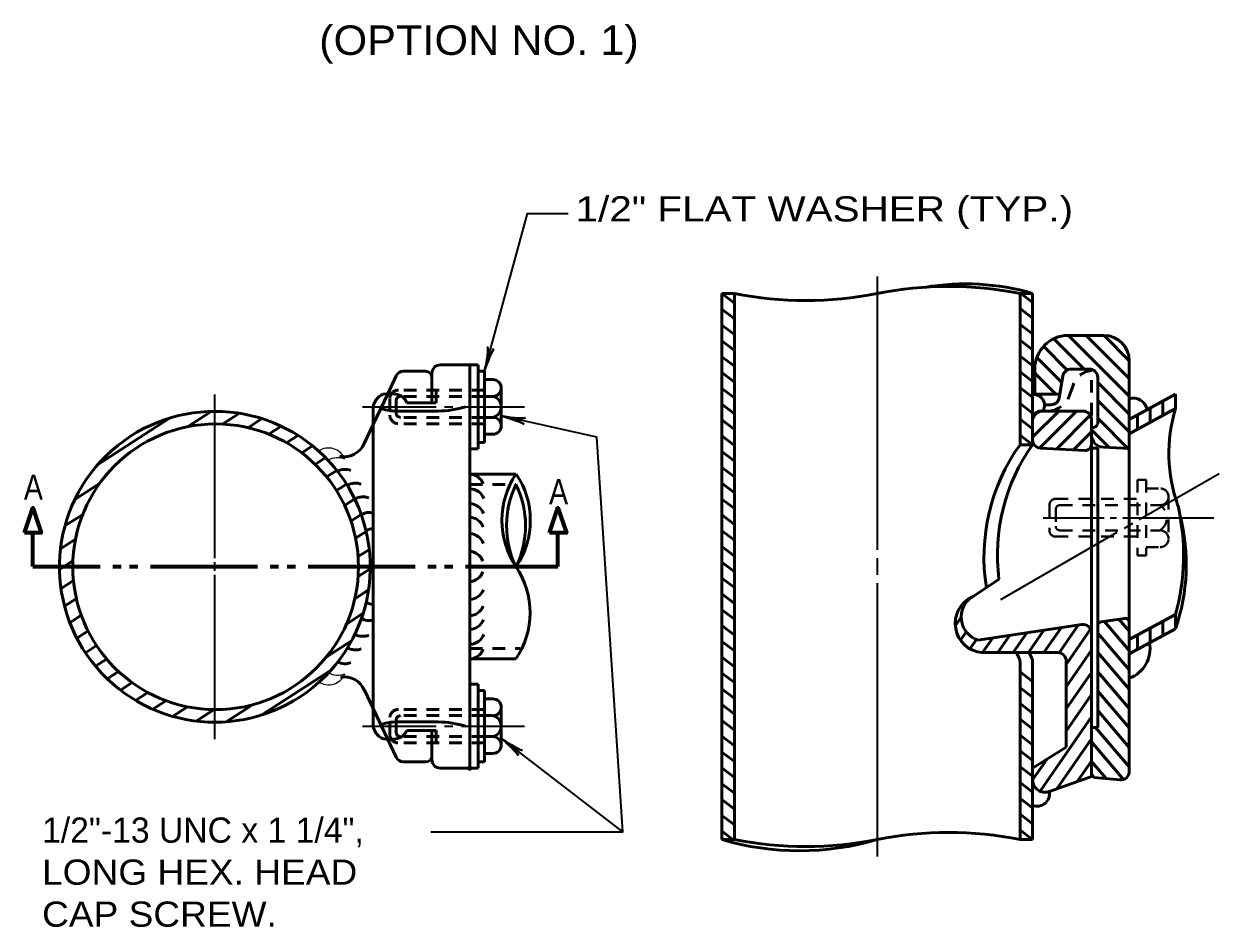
# Model space of a CAD drawing. Extents: x -1 to 679, y 1 to 441.
# Drawn here: x 364.9 to 507.1, y 223.3 to 330.8 of the extents above; entities that cross this region are included whole.
import ezdxf
from ezdxf.enums import TextEntityAlignment as Align

# ---------------------------------------------------------------- set-up
doc = ezdxf.new("R2010")
doc.units = 0
doc.header["$PDMODE"] = 32
doc.header["$PDSIZE"] = 0.5
doc.linetypes.add('LONG_DASHED', pattern=[7.5, 6, -1.5])
doc.linetypes.add('SHORT_DASHED', pattern=[2.7, 1.5, -1.2])
doc.layers.add('1', color=7, linetype='Continuous', lineweight=13)

msp = doc.modelspace()

# ---------------------------------------------------------------- linework, layer by layer
at = {"layer": '1', "lineweight": 35}
for p, q in [((466.424, 300.739), (466.424, 268.239)), ((387.59, 267.239), (387.59, 286.708)), ((405.174, 285.239), (413.924, 285.239)), ((414.924, 285.239), (415.924, 285.239)), ((416.924, 285.239), (424.424, 285.239)), ((497.597, 271.818), (507.123, 277.318)), ((486.174, 272.043), (493.424, 272.043)), ((494.174, 272.043), (494.924, 272.043)), ((495.674, 272.043), (506.516, 272.043)), ((481.142, 262.318), (494.999, 270.318)), ((495.865, 270.818), (496.848, 271.385)), ((387.59, 265.739), (387.59, 266.739)), ((466.424, 267.239), (466.424, 265.239)), ((387.59, 245.708), (387.59, 265.239)), ((466.424, 264.239), (466.424, 231.739)), ((405.174, 247.239), (413.924, 247.239)), ((414.924, 247.239), (415.924, 247.239)), ((416.924, 247.239), (424.424, 247.239))]:
    msp.add_line(p, q, dxfattribs=at)
at = {"layer": '1', "lineweight": 53}
for p, q in [((484.924, 297.679), (483.424, 298.816)), ((447.924, 298.739), (447.924, 233.739)), ((447.924, 298.739), (449.424, 298.739)), ((449.424, 297.602), (447.924, 298.739)), ((449.424, 298.739), (449.424, 233.739)), ((483.424, 298.739), (484.924, 298.739)), ((483.424, 298.739), (483.424, 280.739)), ((449.424, 295.72), (447.924, 296.857)), ((484.924, 295.796), (483.424, 296.933)), ((449.424, 293.837), (447.924, 294.974)), ((484.924, 293.914), (483.424, 295.051)), ((449.424, 291.955), (447.924, 293.092)), ((484.924, 292.032), (483.424, 293.169)), ((487.451, 293.348), (491.06, 289.739)), ((489.174, 293.739), (493.424, 293.739)), ((489.182, 293.739), (496.424, 286.496)), ((491.303, 293.739), (496.424, 288.618)), ((493.424, 293.739), (496.424, 290.739)), ((486.231, 292.447), (489.055, 289.623)), ((414.424, 290.239), (418.924, 290.239)), ((417.924, 290.239), (417.924, 242.239)), ((418.924, 280.239), (418.924, 290.239)), ((449.424, 290.073), (447.924, 291.21)), ((484.924, 290.15), (483.424, 291.287)), ((485.425, 291.132), (488.409, 288.147)), ((496.424, 290.739), (496.424, 283.739)), ((408.155, 286.81), (409.153, 288.917)), ((410.057, 289.489), (412.674, 289.489)), ((413.424, 289.239), (413.424, 285.739)), ((419.674, 289.489), (418.924, 289.489)), ((419.674, 280.989), (419.674, 289.489)), ((449.424, 288.191), (447.924, 289.328)), ((484.924, 288.268), (483.424, 289.405)), ((485.174, 289.739), (485.174, 286.739)), ((485.174, 289.261), (487.696, 286.739)), ((488.535, 288.903), (488.105, 286.324)), ((489.521, 289.739), (491.674, 289.739)), ((420.674, 288.489), (419.674, 288.489)), ((421.674, 287.489), (421.674, 282.989)), ((449.424, 286.308), (447.924, 287.445)), ((484.924, 286.385), (483.424, 287.522)), ((492.674, 288.739), (492.674, 283.239)), ((492.674, 288.125), (496.424, 284.375)), ((413.924, 285.739), (413.924, 287.239)), ((420.674, 286.489), (419.674, 286.489)), ((485.174, 286.739), (488.174, 286.739)), ((492.674, 286.003), (496.424, 282.253)), ((496.424, 283.739), (501.924, 286.739)), ((501.924, 286.739), (501.924, 285.03)), ((384.33, 282.876), (387.16, 284.703)), ((406.424, 284.989), (406.424, 247.489)), ((414.174, 284.739), (409.674, 284.739)), ((413.924, 285.739), (410.424, 285.739)), ((449.424, 284.426), (447.924, 285.563)), ((484.924, 284.503), (483.424, 285.64)), ((488.046, 284.739), (484.924, 281.618)), ((485.065, 284.376), (485.46, 284.639)), ((490.167, 284.739), (485.763, 280.335)), ((485.924, 284.739), (490.924, 284.739)), ((487.119, 285.489), (486.348, 285.481)), ((496.424, 282.03), (501.924, 285.03)), ((498.924, 285.102), (498.924, 283.394)), ((500.424, 285.921), (500.424, 284.212)), ((373.621, 278.343), (382.08, 283.804)), ((388.501, 283.188), (390.499, 284.478)), ((391.532, 282.764), (393.195, 283.838)), ((405.352, 280.892), (406.424, 283.156)), ((420.674, 283.989), (419.674, 283.989)), ((449.424, 282.544), (447.924, 283.681)), ((484.924, 282.621), (483.424, 283.758)), ((485.355, 284.534), (485.223, 284.402)), ((491.789, 284.24), (487.772, 280.223)), ((491.924, 283.739), (491.924, 280.077)), ((492.674, 283.882), (496.424, 280.132)), ((497.424, 284.284), (497.424, 282.576)), ((394.01, 281.983), (395.488, 282.937)), ((396.117, 280.963), (397.479, 281.843)), ((420.674, 281.989), (419.674, 281.989)), ((449.424, 280.662), (447.924, 281.799)), ((484.924, 280.739), (483.424, 281.876)), ((491.924, 282.254), (489.787, 280.117)), ((491.924, 282.511), (494.042, 280.393)), ((397.939, 279.759), (399.226, 280.59)), ((419.674, 280.989), (418.924, 280.989)), ((483.424, 280.739), (484.924, 280.739)), ((485.872, 280.323), (491.135, 280.046)), ((492.674, 280.315), (491.924, 280.315)), ((493.345, 280.43), (496.424, 280.268)), ((399.522, 278.4), (400.76, 279.2)), ((417.924, 280.239), (418.924, 280.239)), ((449.424, 278.779), (447.924, 279.916)), ((491.924, 280.077), (491.924, 241.591)), ((400.889, 276.902), (402.1, 277.684)), ((449.424, 276.897), (447.924, 278.034)), ((370.911, 274.213), (373.861, 276.117)), ((402.055, 275.274), (403.255, 276.049)), ((417.924, 277.239), (423.424, 277.239)), ((449.424, 275.015), (447.924, 276.152)), ((403.022, 273.518), (404.228, 274.296)), ((449.424, 273.133), (447.924, 274.27)), ((369.742, 271.077), (371.859, 272.444)), ((403.786, 271.631), (405.014, 272.424)), ((449.424, 271.251), (447.924, 272.388)), ((404.332, 269.602), (405.603, 270.423)), ((449.424, 269.368), (447.924, 270.505)), ((369.215, 268.356), (370.998, 269.507)), ((404.631, 267.415), (405.973, 268.282)), ((449.424, 267.486), (447.924, 268.623)), ((369.092, 265.897), (370.69, 266.928)), ((449.424, 265.604), (447.924, 266.741)), ((404.634, 265.036), (406.088, 265.975)), ((449.424, 263.722), (447.924, 264.859)), ((480.924, 264.739), (477.76, 262.63)), ((369.27, 263.631), (370.752, 264.587)), ((404.243, 262.403), (405.885, 263.464)), ((369.693, 261.523), (371.099, 262.431)), ((449.424, 261.839), (447.924, 262.976)), ((370.328, 259.553), (371.686, 260.43)), ((403.241, 259.376), (405.241, 260.667)), ((449.424, 259.957), (447.924, 261.094)), ((496.424, 257.54), (501.924, 260.54)), ((501.924, 260.54), (501.924, 258.831)), ((449.424, 258.075), (447.924, 259.212)), ((475.728, 259.214), (476.425, 260.223)), ((478.424, 257.489), (490.778, 259.319)), ((486.262, 255.989), (488.311, 258.954)), ((488.077, 255.977), (490.342, 259.254)), ((493.101, 259.663), (495.851, 260.071)), ((493.448, 259.715), (496.424, 256.241)), ((495.195, 259.981), (496.457, 258.509)), ((500.424, 259.722), (500.424, 258.013)), ((371.158, 257.708), (372.488, 258.567)), ((476.345, 257.468), (477.029, 258.457)), ((477.461, 256.444), (478.23, 257.558)), ((478.969, 255.989), (480.186, 257.75)), ((480.793, 255.989), (482.217, 258.051)), ((482.616, 255.989), (484.248, 258.352)), ((484.439, 255.989), (486.28, 258.653)), ((488.924, 254.564), (491.825, 258.763)), ((492.674, 258.312), (496.424, 253.936)), ((496.424, 255.831), (501.924, 258.831)), ((497.424, 258.085), (497.424, 256.377)), ((498.924, 258.903), (498.924, 257.195)), ((372.173, 255.982), (373.492, 256.834)), ((400.826, 255.436), (403.854, 257.391)), ((449.424, 256.193), (447.924, 257.33)), ((488.924, 251.925), (491.924, 256.267)), ((496.424, 255.831), (498.841, 257.149)), ((373.369, 254.374), (374.694, 255.23)), ((417.924, 255.239), (423.424, 255.239)), ((449.424, 254.31), (447.924, 255.447)), ((478.924, 255.989), (487.924, 255.989)), ((483.424, 233.739), (483.424, 254.739)), ((484.924, 254.739), (484.924, 237.449)), ((488.924, 254.989), (488.924, 244.739)), ((492.674, 256.007), (496.424, 251.631)), ((496.424, 255.831), (496.424, 241.836)), ((496.424, 252.937), (496.424, 255.831)), ((374.753, 252.887), (376.1, 253.757)), ((393.17, 248.569), (401.368, 253.862)), ((449.424, 252.428), (447.924, 253.565)), ((484.924, 252.561), (483.424, 253.698)), ((488.924, 249.286), (491.924, 253.628)), ((492.674, 253.702), (496.424, 249.325)), ((376.333, 251.527), (377.724, 252.424)), ((417.924, 252.239), (418.924, 252.239)), ((418.924, 252.239), (418.924, 242.239)), ((378.133, 250.308), (379.594, 251.251)), ((405.388, 251.51), (406.424, 249.322)), ((419.674, 251.489), (418.924, 251.489)), ((419.674, 251.489), (419.674, 242.989)), ((420.674, 250.489), (419.674, 250.489)), ((449.424, 250.546), (447.924, 251.683)), ((484.924, 250.679), (483.424, 251.816)), ((488.924, 246.647), (491.924, 250.99)), ((492.674, 251.396), (496.424, 247.02)), ((380.187, 249.254), (381.761, 250.27)), ((382.56, 248.405), (384.321, 249.542)), ((385.374, 247.841), (387.493, 249.209)), ((388.93, 247.756), (392.077, 249.788)), ((421.674, 244.989), (421.674, 249.489)), ((449.424, 248.664), (447.924, 249.801)), ((484.924, 248.796), (483.424, 249.933)), ((492.674, 249.091), (496.424, 244.715)), ((414.174, 247.739), (409.674, 247.739)), ((420.674, 248.489), (419.674, 248.489)), ((449.424, 246.781), (447.924, 247.918)), ((484.924, 246.914), (483.424, 248.051)), ((485.809, 239.499), (491.924, 248.351)), ((413.924, 246.739), (410.424, 246.739)), ((413.424, 243.239), (413.424, 246.739)), ((413.924, 246.739), (413.924, 245.239)), ((484.924, 245.032), (483.424, 246.169)), ((492.674, 247.091), (491.924, 247.091)), ((492.413, 247.091), (496.424, 242.409)), ((408.155, 245.668), (409.153, 243.561)), ((420.674, 245.989), (419.674, 245.989)), ((449.424, 244.899), (447.924, 246.036)), ((484.924, 242.239), (488.924, 244.739)), ((487.821, 239.773), (491.924, 245.712)), ((491.924, 245.356), (495.75, 240.89)), ((420.674, 243.989), (419.674, 243.989)), ((449.424, 243.017), (447.924, 244.154)), ((484.924, 243.15), (483.424, 244.287)), ((484.924, 240.858), (486.603, 243.288)), ((410.057, 242.989), (412.674, 242.989)), ((414.424, 242.239), (418.924, 242.239)), ((419.674, 242.989), (418.924, 242.989)), ((449.424, 241.135), (447.924, 242.272)), ((484.924, 241.268), (483.424, 242.405)), ((490.242, 240.638), (491.924, 243.073)), ((491.924, 243.05), (493.69, 240.99)), ((484.924, 239.385), (483.424, 240.522)), ((484.924, 240.867), (484.924, 233.739)), ((484.925, 237.816), (484.924, 240.867)), ((484.925, 237.816), (484.924, 240.867)), ((486.929, 239.455), (492.034, 241.278)), ((491.924, 241.591), (492.256, 241.12)), ((492.256, 241.12), (495.333, 240.84)), ((449.424, 239.253), (447.924, 240.39)), ((486.929, 239.455), (487.01, 239.484)), ((449.424, 237.37), (447.924, 238.507)), ((484.924, 237.503), (483.424, 238.64)), ((449.424, 235.488), (447.924, 236.625)), ((484.924, 235.621), (483.424, 236.758)), ((484.924, 233.739), (483.424, 234.876)), ((449.249, 233.739), (447.924, 234.743)), ((447.924, 233.739), (449.424, 233.739)), ((483.424, 233.739), (484.924, 233.739))]:
    msp.add_line(p, q, dxfattribs=at)
at = {"layer": '1', "linetype": 'SHORT_DASHED', "lineweight": 53}
for p, q in [((491.924, 284.231), (491.924, 289.565)), ((489.682, 287.586), (489.277, 286.502)), ((408.424, 286.239), (408.424, 284.239)), ((409.174, 284.489), (409.174, 285.989)), ((419.674, 287.239), (409.424, 287.239)), ((419.674, 286.489), (409.674, 286.489)), ((419.674, 283.239), (409.424, 283.239)), ((419.674, 283.989), (409.674, 283.989)), ((417.924, 275.989), (423.424, 275.989)), ((417.924, 256.489), (423.924, 256.489)), ((419.674, 249.239), (409.424, 249.239)), ((408.424, 246.239), (408.424, 248.239)), ((409.174, 247.989), (409.174, 246.489)), ((419.674, 248.489), (409.674, 248.489)), ((419.674, 245.239), (409.424, 245.239)), ((419.674, 245.989), (409.674, 245.989))]:
    msp.add_line(p, q, dxfattribs=at)
at = {"layer": '1', "linetype": 'LONG_DASHED', "lineweight": 53}
for p, q in [((406.424, 283.155), (408.155, 286.81)), ((406.424, 249.322), (408.155, 245.668))]:
    msp.add_line(p, q, dxfattribs=at)
at = {"layer": '1', "linetype": 'SHORT_DASHED', "lineweight": 40}
for p, q in [((497.424, 276.543), (498.424, 276.543)), ((497.424, 276.543), (497.424, 267.543)), ((498.424, 276.543), (498.424, 267.543)), ((498.424, 275.543), (500.108, 275.543)), ((486.924, 273.543), (486.924, 270.543)), ((487.674, 274.293), (497.424, 274.293)), ((488.174, 273.543), (500.108, 273.543)), ((501.108, 274.543), (501.108, 269.543)), ((487.674, 273.043), (487.674, 271.043)), ((488.174, 270.543), (500.108, 270.543)), ((487.674, 269.793), (497.424, 269.793)), ((497.424, 267.543), (498.424, 267.543)), ((498.424, 268.543), (500.108, 268.543))]:
    msp.add_line(p, q, dxfattribs=at)
at = {"layer": '1', "lineweight": 70}
for p, q in [((365.924, 266.239), (365.924, 270.239)), ((428.424, 266.239), (428.424, 270.239)), ((365.924, 266.239), (373.924, 266.239)), ((375.424, 266.239), (376.424, 266.239)), ((377.424, 266.239), (378.424, 266.239)), ((379.924, 266.239), (392.674, 266.239)), ((394.174, 266.239), (395.174, 266.239)), ((396.174, 266.239), (397.174, 266.239)), ((398.674, 266.239), (411.424, 266.239)), ((412.924, 266.239), (413.924, 266.239)), ((414.924, 266.239), (415.924, 266.239)), ((417.424, 266.239), (428.424, 266.239))]:
    msp.add_line(p, q, dxfattribs=at)
at = {"layer": '1'}
msp.add_line((379.924, 266.239), (392.674, 266.239), dxfattribs=at)
at = {"layer": '1', "lineweight": 35}
for points in [[(419.674, 289.489), (424.788, 308.252), (429.637, 308.252)], [(436.166, 234.649), (433.067, 281.622), (421.674, 284.168)], [(413.283, 234.649), (436.166, 234.649), (421.674, 245.791)]]:
    msp.add_lwpolyline(points, dxfattribs=at)
at = {"layer": '1', "lineweight": 53}
for points in [[(484.924, 298.739), (484.924, 283.739), (484.924, 280.739)], [(484.924, 283.739), (484.924, 287.045), (484.95, 286.705)], [(498.601, 284.926), (496.424, 283.739), (496.424, 286.212), (496.424, 286.212)], [(486.168, 284.778), (486.064, 284.787), (485.433, 284.608), (485.565, 284.618), (485.367, 284.533), (485.264, 284.429), (485.339, 284.401), (485.103, 284.307), (484.962, 283.911)], [(486.003, 284.739), (485.924, 284.739), (486.173, 284.802)], [(496.424, 283.739), (496.424, 282.03), (496.424, 257.54), (496.424, 255.831)], [(492.674, 280.315), (492.674, 259.168), (492.674, 247.091)]]:
    msp.add_lwpolyline(points, dxfattribs=at)
at = {"layer": '1', "lineweight": 70}
for points in [[(364.924, 270.239), (365.924, 273.239), (366.924, 270.239)], [(427.424, 270.239), (428.424, 273.239), (429.424, 270.239)]]:
    msp.add_lwpolyline(points, close=True, dxfattribs=at)
at = {"layer": '1', "lineweight": 53}
msp.add_circle((387.674, 266.208), 17, dxfattribs=at)
for centre, radius, start, end in [((474.924, 256.102), 43.476, 78.72544, 101.27456), ((476.959, 271.547), 28.334, 73.67307, 99.88388), ((457.924, 341.376), 43.476, 258.72544, 281.27456), ((489.174, 289.739), 4, 90, 180), ((493.424, 290.739), 3, 0, 90), ((414.424, 289.239), 1, 90, 180), ((410.057, 288.489), 1, 90, 154.65229), ((412.674, 288.739), 0.75, 0, 90), ((489.521, 288.739), 1, 90, 170.53768), ((491.674, 288.739), 1, 0, 90), ((420.674, 287.489), 1, 0, 90), ((420.674, 287.48), 1, 270, 0), ((408.295, 284.994), 1.87, 111.08869, 180.15219), ((408.372, 283.136), 3.68, 78.23971, 101.76029), ((409.001, 285.233), 1.51, 19.5508, 85.42547), ((420.399, 285.239), 1.28, 282.40625, 77.59375), ((485.082, 285.446), 1.266, 329.43434, 96.01658), ((487.119, 286.489), 1, 270, 350.53836), ((496.906, 284.604), 1.679, 10.62414, 106.70314), ((387.59, 266.208), 18.5, 42.84859, 309.02179), ((409.289, 290.721), 5.994, 250.874, 273.68302), ((413.971, 296.938), 12.201, 270.95318, 286.48773), ((485.924, 283.739), 1, 90, 180), ((486.271, 283.392), 1.391, 104.44111, 165.55889), ((486.004, 283.78), 1.012, 107.64312, 154.39534), ((485.899, 284.055), 0.681, 97.5146, 146.7228), ((485.388, 284.706), 0.176, 260.06059, 322.47031), ((485.243, 285.622), 1.043, 278.38082, 293.49085), ((490.924, 283.739), 1, 0, 90), ((519.841, 279.719), 18.688, 163.48944, 199.55179), ((420.674, 283.002), 1, 0, 90), ((483.952, 284.747), 1.279, 320.82126, 345.1698), ((485.818, 283.734), 0.885, 132.01704, 165.33257), ((488.771, 281.406), 4.606, 138.35366, 144.36072), ((492.054, 283.393), 0.639, 260.57519, 346.02951), ((420.674, 282.989), 1, 270, 0), ((493.424, 281.928), 1.5, 180, 266.9852), ((402.978, 281.866), 2.566, 257.68223, 337.70907), ((502.092, 267.376), 22.958, 144.40401, 189.11494), ((503.308, 267.643), 22.572, 144.53567, 187.39184), ((485.924, 281.322), 1, 180, 266.98501), ((491.174, 280.795), 0.75, 266.98584, 0), ((387.59, 266.208), 18.5, 309.02189, 42.84853), ((403.068, 275.998), 1.81, 67.15515, 119.23791), ((404.308, 274.353), 1.81, 67.15515, 121.81596), ((417.836, 275.431), 1.81, 21.06434, 87.22086), ((431.62, 271.739), 9.87, 146.13542, 213.86458), ((415.264, 271.739), 9.87, 326.13542, 33.86458), ((417.898, 273.689), 1.81, 21.06434, 87.22086), ((433.665, 271.076), 11.358, 154.3728, 205.20801), ((413.426, 271.077), 11.139, 334.25624, 26.16295), ((405.193, 272.733), 1.81, 67.15515, 120.65847), ((417.867, 271.917), 1.81, 21.06434, 87.22086), ((476.666, 267.606), 26.228, 344.37008, 12.90873), ((405.952, 270.86), 1.81, 74.88502, 121.03631), ((417.836, 270.298), 1.81, 21.06434, 87.22086), ((479.962, 266.465), 23.252, 340.83222, 14.49037), ((406.585, 268.962), 1.81, 95.08372, 123.29121), ((417.867, 268.343), 1.81, 21.06434, 87.22086), ((417.806, 266.235), 1.81, 21.06434, 87.22086), ((415.228, 260.739), 9.87, 326.13542, 33.86458), ((417.806, 266.241), 1.81, 272.77914, 338.93566), ((417.867, 264.133), 1.81, 272.77914, 338.93566), ((406.585, 263.508), 1.81, 236.70879, 264.91628), ((479.202, 259.46), 3.482, 114.45413, 265.43129), ((479.28, 260.213), 2.855, 122.16994, 252.55173), ((417.836, 262.178), 1.81, 272.77914, 338.93566), ((405.952, 261.61), 1.81, 238.96369, 285.11497), ((417.867, 260.559), 1.81, 272.77914, 338.93566), ((490.924, 258.33), 1, 0, 98.42688), ((493.174, 259.169), 0.5, 98.42904, 180), ((495.924, 259.576), 0.5, 0, 98.42709), ((405.193, 259.738), 1.81, 239.34153, 292.84485), ((417.898, 258.787), 1.81, 272.77914, 338.93566), ((404.308, 258.118), 1.81, 238.18404, 292.84485), ((417.836, 257.046), 1.81, 272.77914, 338.93566), ((495.134, 256.477), 3.767, 290.03142, 10.27964), ((403.068, 256.473), 1.81, 240.76209, 292.84485), ((481.634, 254.748), 1.79, 359.71435, 43.88847), ((483.134, 254.748), 1.79, 359.71435, 43.88847), ((487.924, 254.989), 1, 0, 90), ((403.001, 250.531), 2.566, 22.29093, 100.21406), ((420.674, 249.489), 1, 0, 90), ((420.674, 249.475), 1, 270, 0), ((409.289, 241.757), 5.994, 86.31698, 109.126), ((413.971, 235.54), 12.201, 73.51227, 89.04682), ((420.399, 247.239), 1.28, 282.40625, 77.59375), ((408.295, 247.484), 1.87, 179.84781, 248.91131), ((409.001, 247.244), 1.51, 274.57453, 340.4492), ((408.372, 249.341), 3.68, 258.23971, 281.76029), ((420.674, 244.998), 1, 0, 90), ((420.674, 244.989), 1, 270, 0), ((410.057, 243.989), 1, 205.34771, 270), ((412.674, 243.739), 0.75, 270, 0), ((414.424, 243.239), 1, 180, 270), ((486.424, 240.867), 1.5, 180, 288.30571), ((486.424, 240.867), 1.5, 180, 288.30571), ((492.424, 241.591), 0.5, 180, 250.34668), ((495.424, 241.836), 1, 264.79006, 0), ((485.463, 239.203), 1.488, 248.82416, 9.72636), ((485.463, 239.203), 1.488, 248.82416, 9.72636), ((457.174, 265.241), 32.832, 253.63622, 286.36377), ((457.924, 276.376), 43.476, 258.72544, 281.27456), ((474.924, 191.102), 43.476, 78.72544, 101.27456)]:
    msp.add_arc(centre, radius, start, end, dxfattribs=at)
at = {"layer": '1', "linetype": 'SHORT_DASHED', "lineweight": 53}
for centre, radius, start, end in [((492.19, 287.003), 2.575, 95.92601, 166.92161), ((409.424, 286.239), 1, 90, 180), ((409.674, 285.989), 0.5, 90, 180), ((486.6, 287.621), 2.9, 276.48502, 337.3181), ((409.424, 284.239), 1, 180, 270), ((409.674, 284.489), 0.5, 180, 270), ((409.424, 248.239), 1, 90, 180), ((409.674, 247.989), 0.5, 90, 180), ((409.424, 246.239), 1, 180, 270), ((409.674, 246.489), 0.5, 180, 270)]:
    msp.add_arc(centre, radius, start, end, dxfattribs=at)
at = {"layer": '1'}
for centre, radius, start, end in [((401.125, 278.277), 2.069, 21.01512, 125.21688), ((392.883, 271.273), 11.193, 42.84853, 50.96996), ((402.206, 277), 2.191, 67.15515, 120.65847), ((392.883, 261.224), 11.193, 309.03004, 317.15147), ((401.125, 254.22), 2.069, 234.78312, 338.98488), ((402.206, 255.497), 2.191, 239.34153, 292.84485)]:
    msp.add_arc(centre, radius, start, end, dxfattribs=at)
at = {"layer": '1', "linetype": 'SHORT_DASHED', "lineweight": 40}
for centre, radius, start, end in [((500.108, 274.543), 1, 0, 90), ((487.674, 273.543), 0.75, 90, 180), ((488.174, 273.043), 0.5, 90, 180), ((499.08, 272.043), 1.818, 304.40161, 55.59839), ((500.108, 274.543), 1, 270, 0), ((487.674, 270.543), 0.75, 180, 270), ((488.174, 271.043), 0.5, 180, 270), ((500.108, 269.543), 1, 0, 90), ((500.108, 269.543), 1, 270, 0)]:
    msp.add_arc(centre, radius, start, end, dxfattribs=at)
at = {"layer": '1', "lineweight": 40}
for centre, major_axis, ratio, start_param, end_param in [((419.695, 290.614), (-0.319, -1.764), 0.122415, 0.8963533, 3.1415927), ((420.173, 290.514), (-0.631, -1.648), 0.07063, 3.1407148, 5.41811), ((422.722, 283.717), (1.676, -0.554), 0.07063, 6.2823074, 8.5597026), ((422.799, 284.2), (-1.777, 0.237), 0.122415, 0.8963533, 3.1415927), ((422.434, 244.94), (1.285, -1.21), 0.07063, 6.2823074, 8.5597026), ((422.708, 245.345), (-1.511, 0.965), 0.122415, 0.8963533, 3.1415927)]:
    msp.add_ellipse(centre, major_axis=major_axis, ratio=ratio, start_param=start_param, end_param=end_param, dxfattribs=at)
at = {"layer": '1'}
msp.add_point((417.924, 242.239), dxfattribs=at)

# ---------------------------------------------------------------- texts
at = {"layer": '1', "width": 1.1}
msp.add_text('(OPTION NO. 1)', height=3.5, dxfattribs=at).set_placement((419.018, 327.134), align=Align.CENTER)
at = {"layer": '1'}
for s, width, p in [('1/2" FLAT WASHER (TYP.)', 1.2, (430.522, 307.303)), ('A', 0.85, (364.847, 274.182)), ('A', 0.85, (427.364, 273.64)), ('LONG HEX. HEAD', 1.1, (367.016, 228.366)), ('CAP SCREW.', 1.1, (367.016, 223.366))]:
    msp.add_text(s, height=3, dxfattribs=dict(at, width=width)).set_placement(p)
msp.add_text('1/2"-13 UNC x 1 1/4",', height=3, dxfattribs=at).set_placement((367.016, 233.366))

doc.saveas('drawing.dxf')
